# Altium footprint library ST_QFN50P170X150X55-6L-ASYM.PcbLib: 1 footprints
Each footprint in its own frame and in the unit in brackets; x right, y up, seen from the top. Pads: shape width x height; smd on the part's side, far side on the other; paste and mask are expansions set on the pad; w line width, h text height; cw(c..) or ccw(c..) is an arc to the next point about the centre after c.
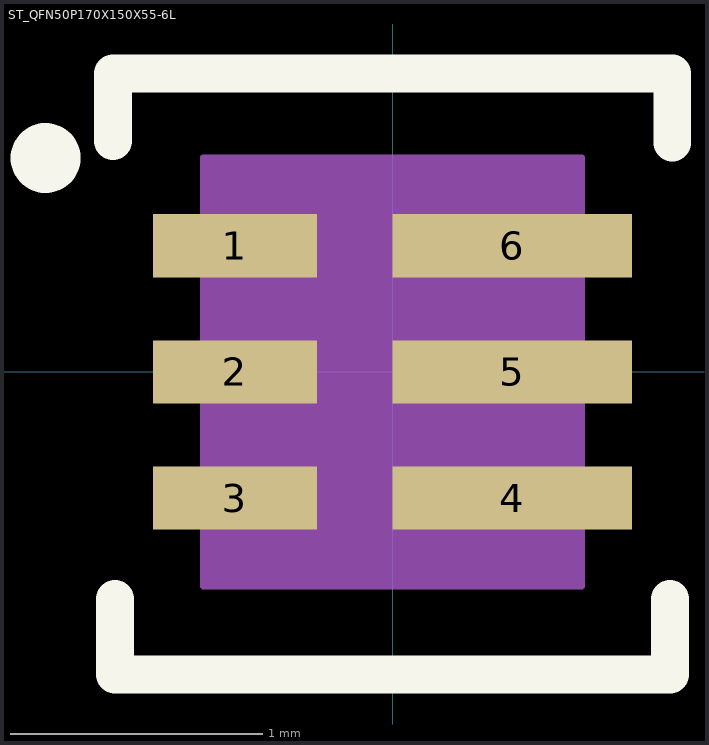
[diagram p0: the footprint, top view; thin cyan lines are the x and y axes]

## ST_QFN50P170X150X55-6L [mm] "ST_QFN50P170X150X55-6L"
pads (6):
  rect 0.65x0.25 smd paste-20 mask+0.05: 1(-0.625,0.5) 2(-0.625,0) 3(-0.625,-0.5)
  rect 0.95x0.25 smd paste-20 mask+0.05: 4(0.475,-0.5) 5(0.475,0) 6(0.475,0.5)
Top Overlay:
  circle w0.2: c-1.376,0.848 r0.038
  lines w0.15: -1.109,0.916 -1.109,1.183 1.108,1.183 1.108,0.908 ; -1.1,-0.9 -1.1,-1.1 -1.1,-1.2 1.1,-1.2 1.1,-0.9
Top Paste:
  rectangle: -0.935,0.38 -0.315,0.62
  rectangle: -0.935,-0.12 -0.315,0.12
  rectangle: -0.935,-0.62 -0.315,-0.38
  rectangle: 0.025,-0.62 0.925,-0.38
  rectangle: 0.025,-0.12 0.925,0.12
  rectangle: 0.025,0.38 0.925,0.62
Mechanical 5:
  text "4" at 1.154,-0.45 h0.1
  text "3" at -1.247,-0.4 h0.1
  text "5" at 1.154,0.05 h0.1
  text "2" at -1.247,0.1 h0.1
  text "6" at 1.154,0.6 h0.1
  text "1" at -1.247,0.6 h0.1
Mechanical 6:
  lines w0.025: -0.75,-0.85 -0.75,0.85 0.75,0.85 0.75,-0.85 -0.75,-0.85
Mechanical 7:
  region: -0.75,0.85 -0.75,-0.85 0.75,-0.85 0.75,0.85
Mechanical 15:
  lines w0.001: -0.5,0 0.5,0 ; 0,-0.5 0,0.5
3D body: height 0.55, standoff 0, extent -0.75,-0.85 0.75,0.85
3D body "DFN_170x150x55-6L_asym.STEP": height 0.56, standoff 0.01, extent -0.75,-0.85 0.75,0.85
